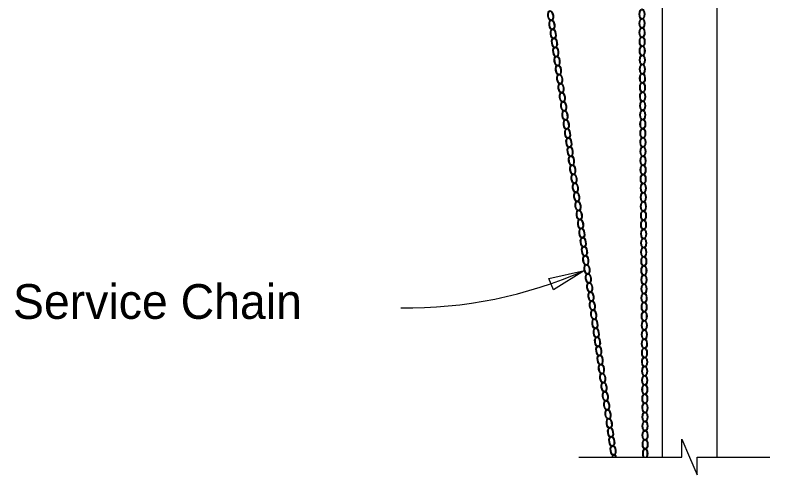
# Model space of a CAD drawing. Extents: x 83976.6 to 84012, y 72958.9 to 72975.6.
# Drawn here: x 83993.594 to 83995.786, y 72963.229 to 72964.564 of the extents above; entities that cross this region are included whole.
import ezdxf

# ---------------------------------------------------------------- set-up
doc = ezdxf.new("R2010")
doc.units = 0
for name, color, linetype in [('DSText', 7, 'Continuous'), ('DSTitle', 7, 'Continuous'), ('Patterning', 7, 'Continuous'), ('SheetLines_dp', 7, 'Continuous')]:
    doc.layers.add(name, color=color, linetype=linetype)

msp = doc.modelspace()

# ---------------------------------------------------------------- linework, layer by layer
at = {"layer": 'DSText'}
for p, q in [((83995.4736, 72965.9053), (83995.4736, 72963.2807)), ((83995.6319, 72965.9053), (83995.6319, 72963.2807))]:
    msp.add_line(p, q, dxfattribs=at)
at = {"layer": 'DSTitle'}
for centre, major_axis, ratio in [((83995.1494, 72964.5619), (-0.0022, 0.0152), 0.530594), ((83995.1494, 72964.5619), (-0.0019, 0.0131), 0.458548), ((83995.4147, 72964.5661), (-0.0001, 0.0153), 0.530594), ((83995.4147, 72964.5661), (-0.0001, 0.0133), 0.458548), ((83995.1532, 72964.5356), (-0.0022, 0.0152), 0.530594), ((83995.1532, 72964.5356), (-0.0019, 0.0131), 0.458548), ((83995.4149, 72964.5396), (-0.0001, 0.0153), 0.530594), ((83995.4149, 72964.5396), (-0.0001, 0.0133), 0.458548), ((83995.157, 72964.5093), (-0.0022, 0.0152), 0.530594), ((83995.157, 72964.5093), (-0.0019, 0.0131), 0.458548), ((83995.4151, 72964.513), (-0.0001, 0.0153), 0.530594), ((83995.4151, 72964.513), (-0.0001, 0.0133), 0.458548), ((83995.1607, 72964.483), (-0.0022, 0.0152), 0.530594), ((83995.4153, 72964.4864), (-0.0001, 0.0153), 0.530594), ((83995.4153, 72964.4864), (-0.0001, 0.0133), 0.458548), ((83995.1607, 72964.483), (-0.0019, 0.0131), 0.458548), ((83995.1645, 72964.4567), (-0.0022, 0.0152), 0.530594), ((83995.1645, 72964.4567), (-0.0019, 0.0131), 0.458548), ((83995.4155, 72964.4599), (-0.0001, 0.0153), 0.530594), ((83995.4155, 72964.4599), (-0.0001, 0.0133), 0.458548), ((83995.1683, 72964.4304), (-0.0022, 0.0152), 0.530594), ((83995.1683, 72964.4304), (-0.0019, 0.0131), 0.458548), ((83995.4157, 72964.4333), (-0.0001, 0.0153), 0.530594), ((83995.4157, 72964.4333), (-0.0001, 0.0133), 0.458548), ((83995.1721, 72964.4041), (-0.0022, 0.0152), 0.530594), ((83995.1721, 72964.4041), (-0.0019, 0.0131), 0.458548), ((83995.4159, 72964.4067), (-0.0001, 0.0153), 0.530594), ((83995.4159, 72964.4067), (-0.0001, 0.0133), 0.458548), ((83995.1759, 72964.3778), (-0.0022, 0.0152), 0.530594), ((83995.1759, 72964.3778), (-0.0019, 0.0131), 0.458548), ((83995.4161, 72964.3802), (-0.0001, 0.0153), 0.530594), ((83995.4161, 72964.3802), (-0.0001, 0.0133), 0.458548), ((83995.1797, 72964.3515), (-0.0022, 0.0152), 0.530594), ((83995.4163, 72964.3536), (-0.0001, 0.0153), 0.530594), ((83995.4163, 72964.3536), (-0.0001, 0.0133), 0.458548), ((83995.1797, 72964.3515), (-0.0019, 0.0131), 0.458548), ((83995.1834, 72964.3253), (-0.0022, 0.0152), 0.530594), ((83995.1834, 72964.3253), (-0.0019, 0.0131), 0.458548), ((83995.4165, 72964.327), (-0.0001, 0.0153), 0.530594), ((83995.4165, 72964.327), (-0.0001, 0.0133), 0.458548), ((83995.1872, 72964.299), (-0.0022, 0.0152), 0.530594), ((83995.1872, 72964.299), (-0.0019, 0.0131), 0.458548), ((83995.4167, 72964.3005), (-0.0001, 0.0153), 0.530594), ((83995.4167, 72964.3005), (-0.0001, 0.0133), 0.458548), ((83995.191, 72964.2727), (-0.0022, 0.0152), 0.530594), ((83995.191, 72964.2727), (-0.0019, 0.0131), 0.458548), ((83995.4169, 72964.2739), (-0.0001, 0.0153), 0.530594), ((83995.4169, 72964.2739), (-0.0001, 0.0133), 0.458548), ((83995.1948, 72964.2464), (-0.0022, 0.0152), 0.530594), ((83995.1948, 72964.2464), (-0.0019, 0.0131), 0.458548), ((83995.4171, 72964.2473), (-0.0001, 0.0153), 0.530594), ((83995.4171, 72964.2473), (-0.0001, 0.0133), 0.458548), ((83995.1986, 72964.2201), (-0.0022, 0.0152), 0.530594), ((83995.4173, 72964.2208), (-0.0001, 0.0153), 0.530594), ((83995.1986, 72964.2201), (-0.0019, 0.0131), 0.458548), ((83995.4173, 72964.2208), (-0.0001, 0.0133), 0.458548), ((83995.2024, 72964.1938), (-0.0022, 0.0152), 0.530594), ((83995.2024, 72964.1938), (-0.0019, 0.0131), 0.458548), ((83995.4175, 72964.1942), (-0.0001, 0.0153), 0.530594), ((83995.4175, 72964.1942), (-0.0001, 0.0133), 0.458548), ((83995.2061, 72964.1675), (-0.0022, 0.0152), 0.530594), ((83995.2061, 72964.1675), (-0.0019, 0.0131), 0.458548), ((83995.4177, 72964.1676), (-0.0001, 0.0153), 0.530594), ((83995.4177, 72964.1676), (-0.0001, 0.0133), 0.458548), ((83995.2099, 72964.1412), (-0.0022, 0.0152), 0.530594), ((83995.2099, 72964.1412), (-0.0019, 0.0131), 0.458548), ((83995.4179, 72964.1411), (-0.0001, 0.0153), 0.530594), ((83995.4179, 72964.1411), (-0.0001, 0.0133), 0.458548), ((83995.2137, 72964.1149), (-0.0022, 0.0152), 0.530594), ((83995.2137, 72964.1149), (-0.0019, 0.0131), 0.458548), ((83995.4181, 72964.1145), (-0.0001, 0.0153), 0.530594), ((83995.4181, 72964.1145), (-0.0001, 0.0133), 0.458548), ((83995.2175, 72964.0886), (-0.0022, 0.0152), 0.530594), ((83995.2175, 72964.0886), (-0.0019, 0.0131), 0.458548), ((83995.4183, 72964.0879), (-0.0001, 0.0153), 0.530594), ((83995.4183, 72964.0879), (-0.0001, 0.0133), 0.458548), ((83995.2213, 72964.0623), (-0.0022, 0.0152), 0.530594), ((83995.2213, 72964.0623), (-0.0019, 0.0131), 0.458548), ((83995.4185, 72964.0614), (-0.0001, 0.0153), 0.530594), ((83995.4185, 72964.0614), (-0.0001, 0.0133), 0.458548), ((83995.2251, 72964.036), (-0.0022, 0.0152), 0.530594), ((83995.2251, 72964.036), (-0.0019, 0.0131), 0.458548), ((83995.4187, 72964.0348), (-0.0001, 0.0153), 0.530594), ((83995.4187, 72964.0348), (-0.0001, 0.0133), 0.458548), ((83995.2288, 72964.0097), (-0.0022, 0.0152), 0.530594), ((83995.2288, 72964.0097), (-0.0019, 0.0131), 0.458548), ((83995.4189, 72964.0082), (-0.0001, 0.0153), 0.530594), ((83995.4189, 72964.0082), (-0.0001, 0.0133), 0.458548), ((83995.2326, 72963.9834), (-0.0022, 0.0152), 0.530594), ((83995.2326, 72963.9834), (-0.0019, 0.0131), 0.458548), ((83995.4191, 72963.9817), (-0.0001, 0.0153), 0.530594), ((83995.4191, 72963.9817), (-0.0001, 0.0133), 0.458548), ((83995.2364, 72963.9571), (-0.0022, 0.0152), 0.530594), ((83995.2364, 72963.9571), (-0.0019, 0.0131), 0.458548), ((83995.4193, 72963.9551), (-0.0001, 0.0153), 0.530594), ((83995.4193, 72963.9551), (-0.0001, 0.0133), 0.458548), ((83995.2402, 72963.9308), (-0.0022, 0.0152), 0.530594), ((83995.2402, 72963.9308), (-0.0019, 0.0131), 0.458548), ((83995.4195, 72963.9285), (-0.0001, 0.0153), 0.530594), ((83995.4195, 72963.9285), (-0.0001, 0.0133), 0.458548), ((83995.244, 72963.9045), (-0.0022, 0.0152), 0.530594), ((83995.244, 72963.9045), (-0.0019, 0.0131), 0.458548), ((83995.4197, 72963.902), (-0.0001, 0.0153), 0.530594), ((83995.4197, 72963.902), (-0.0001, 0.0133), 0.458548), ((83995.2478, 72963.8782), (-0.0022, 0.0152), 0.530594), ((83995.2478, 72963.8782), (-0.0019, 0.0131), 0.458548), ((83995.4199, 72963.8754), (-0.0001, 0.0153), 0.530594), ((83995.4199, 72963.8754), (-0.0001, 0.0133), 0.458548), ((83995.2515, 72963.8519), (-0.0022, 0.0152), 0.530594), ((83995.2515, 72963.8519), (-0.0019, 0.0131), 0.458548), ((83995.4201, 72963.8488), (-0.0001, 0.0153), 0.530594), ((83995.2553, 72963.8256), (-0.0022, 0.0152), 0.530594), ((83995.4201, 72963.8488), (-0.0001, 0.0133), 0.458548), ((83995.2553, 72963.8256), (-0.0019, 0.0131), 0.458548), ((83995.4203, 72963.8223), (-0.0001, 0.0153), 0.530594), ((83995.4203, 72963.8223), (-0.0001, 0.0133), 0.458548), ((83995.2591, 72963.7993), (-0.0022, 0.0152), 0.530594), ((83995.2591, 72963.7993), (-0.0019, 0.0131), 0.458548), ((83995.4205, 72963.7957), (-0.0001, 0.0153), 0.530594), ((83995.4205, 72963.7957), (-0.0001, 0.0133), 0.458548), ((83995.2629, 72963.773), (-0.0022, 0.0152), 0.530594), ((83995.2629, 72963.773), (-0.0019, 0.0131), 0.458548), ((83995.4207, 72963.7691), (-0.0001, 0.0153), 0.530594), ((83995.4207, 72963.7691), (-0.0001, 0.0133), 0.458548), ((83995.2667, 72963.7467), (-0.0022, 0.0152), 0.530594), ((83995.2667, 72963.7467), (-0.0019, 0.0131), 0.458548), ((83995.4209, 72963.7426), (-0.0001, 0.0153), 0.530594), ((83995.4209, 72963.7426), (-0.0001, 0.0133), 0.458548), ((83995.2705, 72963.7204), (-0.0022, 0.0152), 0.530594), ((83995.2705, 72963.7204), (-0.0019, 0.0131), 0.458548), ((83995.4211, 72963.716), (-0.0001, 0.0153), 0.530594), ((83995.2743, 72963.6942), (-0.0022, 0.0152), 0.530594), ((83995.4211, 72963.716), (-0.0001, 0.0133), 0.458548), ((83995.2743, 72963.6942), (-0.0019, 0.0131), 0.458548), ((83995.4213, 72963.6895), (-0.0001, 0.0153), 0.530594), ((83995.4213, 72963.6895), (-0.0001, 0.0133), 0.458548), ((83995.278, 72963.6679), (-0.0022, 0.0152), 0.530594), ((83995.278, 72963.6679), (-0.0019, 0.0131), 0.458548), ((83995.4215, 72963.6629), (-0.0001, 0.0153), 0.530594), ((83995.4215, 72963.6629), (-0.0001, 0.0133), 0.458548), ((83995.2818, 72963.6416), (-0.0022, 0.0152), 0.530594), ((83995.2818, 72963.6416), (-0.0019, 0.0131), 0.458548), ((83995.4217, 72963.6363), (-0.0001, 0.0153), 0.530594), ((83995.4217, 72963.6363), (-0.0001, 0.0133), 0.458548), ((83995.2856, 72963.6153), (-0.0022, 0.0152), 0.530594), ((83995.2856, 72963.6153), (-0.0019, 0.0131), 0.458548), ((83995.4219, 72963.6098), (-0.0001, 0.0153), 0.530594), ((83995.4219, 72963.6098), (-0.0001, 0.0133), 0.458548), ((83995.2894, 72963.589), (-0.0022, 0.0152), 0.530594), ((83995.2894, 72963.589), (-0.0019, 0.0131), 0.458548), ((83995.2932, 72963.5627), (-0.0022, 0.0152), 0.530594), ((83995.4221, 72963.5832), (-0.0001, 0.0153), 0.530594), ((83995.4221, 72963.5832), (-0.0001, 0.0133), 0.458548), ((83995.2932, 72963.5627), (-0.0019, 0.0131), 0.458548), ((83995.4223, 72963.5566), (-0.0001, 0.0153), 0.530594), ((83995.4223, 72963.5566), (-0.0001, 0.0133), 0.458548), ((83995.297, 72963.5364), (-0.0022, 0.0152), 0.530594), ((83995.297, 72963.5364), (-0.0019, 0.0131), 0.458548), ((83995.4225, 72963.5301), (-0.0001, 0.0153), 0.530594), ((83995.4225, 72963.5301), (-0.0001, 0.0133), 0.458548), ((83995.3007, 72963.5101), (-0.0022, 0.0152), 0.530594), ((83995.3007, 72963.5101), (-0.0019, 0.0131), 0.458548), ((83995.4227, 72963.5035), (-0.0001, 0.0153), 0.530594), ((83995.4227, 72963.5035), (-0.0001, 0.0133), 0.458548), ((83995.3045, 72963.4838), (-0.0022, 0.0152), 0.530594), ((83995.3045, 72963.4838), (-0.0019, 0.0131), 0.458548), ((83995.4229, 72963.4769), (-0.0001, 0.0153), 0.530594), ((83995.4229, 72963.4769), (-0.0001, 0.0133), 0.458548), ((83995.3083, 72963.4575), (-0.0022, 0.0152), 0.530594), ((83995.3083, 72963.4575), (-0.0019, 0.0131), 0.458548), ((83995.3121, 72963.4312), (-0.0022, 0.0152), 0.530594), ((83995.4231, 72963.4504), (-0.0001, 0.0153), 0.530594), ((83995.4231, 72963.4504), (-0.0001, 0.0133), 0.458548), ((83995.3121, 72963.4312), (-0.0019, 0.0131), 0.458548), ((83995.4233, 72963.4238), (-0.0001, 0.0153), 0.530594), ((83995.4233, 72963.4238), (-0.0001, 0.0133), 0.458548), ((83995.3159, 72963.4049), (-0.0022, 0.0152), 0.530594), ((83995.3159, 72963.4049), (-0.0019, 0.0131), 0.458548), ((83995.4235, 72963.3972), (-0.0001, 0.0153), 0.530594), ((83995.4235, 72963.3972), (-0.0001, 0.0133), 0.458548), ((83995.3197, 72963.3786), (-0.0022, 0.0152), 0.530594), ((83995.3197, 72963.3786), (-0.0019, 0.0131), 0.458548), ((83995.4237, 72963.3707), (-0.0001, 0.0153), 0.530594), ((83995.4237, 72963.3707), (-0.0001, 0.0133), 0.458548), ((83995.3234, 72963.3523), (-0.0022, 0.0152), 0.530594), ((83995.3234, 72963.3523), (-0.0019, 0.0131), 0.458548), ((83995.4238, 72963.3441), (-0.0001, 0.0153), 0.530594), ((83995.3272, 72963.326), (-0.0022, 0.0152), 0.530594), ((83995.3272, 72963.326), (-0.0019, 0.0131), 0.458548), ((83995.4238, 72963.3441), (-0.0001, 0.0133), 0.458548), ((83995.331, 72963.2997), (-0.0022, 0.0152), 0.530594), ((83995.424, 72963.3175), (-0.0001, 0.0153), 0.530594), ((83995.424, 72963.3175), (-0.0001, 0.0133), 0.458548), ((83995.331, 72963.2997), (-0.0019, 0.0131), 0.458548)]:
    msp.add_ellipse(centre, major_axis=major_axis, ratio=ratio, dxfattribs=at)
for centre, major_axis, ratio, start_param, end_param in [((83995.4242, 72963.291), (-0.0001, 0.0153), 0.530594, 3.972453, 8.585976), ((83995.4242, 72963.291), (-0.0001, 0.0133), 0.458548, 3.823287, 8.736221), ((83995.3348, 72963.2734), (-0.0022, 0.0152), 0.530594, 5.133487, 7.280477), ((83995.3348, 72963.2734), (-0.0019, 0.0131), 0.458548, 5.229681, 7.204914)]:
    msp.add_ellipse(centre, major_axis=major_axis, ratio=ratio, start_param=start_param, end_param=end_param, dxfattribs=at)
at = {"layer": 'SheetLines_dp'}
msp.add_lwpolyline([(83995.2478, 72963.8219), (83995.1579, 72963.7664), (83995.1446, 72963.7991)], close=True, dxfattribs=at)
msp.add_lwpolyline([(83995.231, 72963.2807), (83995.5303, 72963.2807), (83995.5303, 72963.3323), (83995.5528, 72963.2807), (83995.5753, 72963.229), (83995.5753, 72963.2807), (83995.7863, 72963.2807)], dxfattribs=at)
msp.add_arc((83994.7304, 72965.0029), 1.2893, 269.3111, 293.6545, dxfattribs=at)

# ---------------------------------------------------------------- texts
at = {"layer": 'Patterning'}
msp.add_text('Service Chain', height=0.1008, dxfattribs=at).set_placement((83993.588, 72963.6819))

doc.saveas('drawing.dxf')
